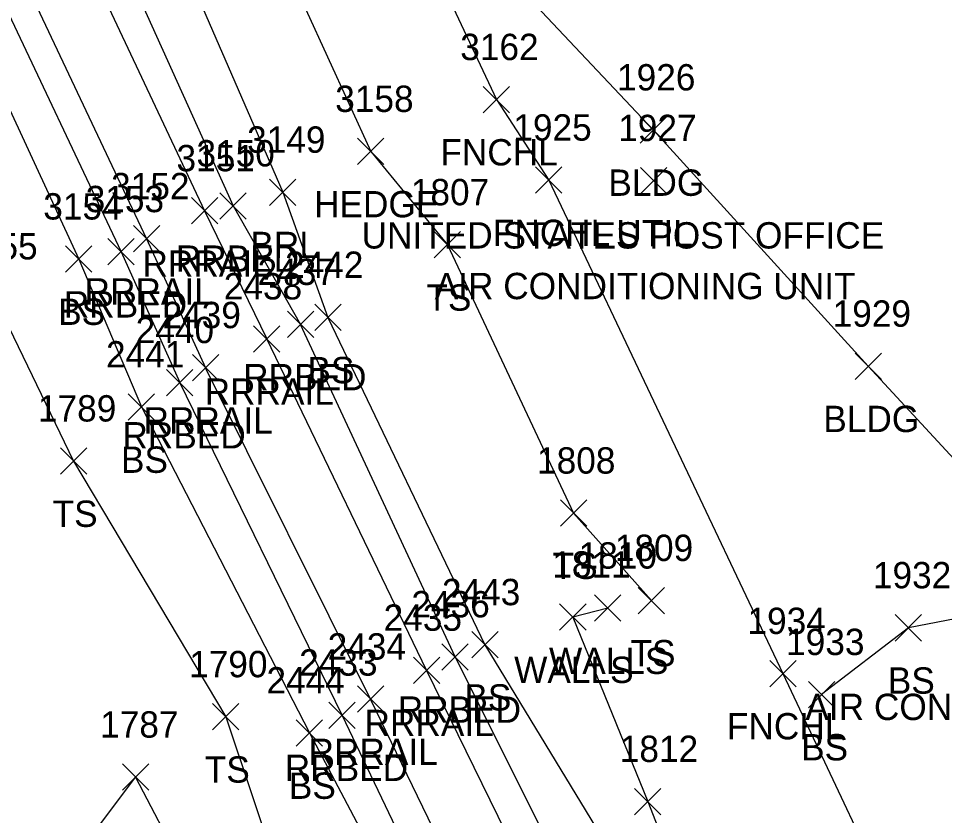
# Model space of a CAD drawing. Extents: x 1462668 to 1465147, y 550359 to 557351.
# Drawn here: x 1464582.5 to 1464652.8, y 552792.1 to 552852.6 of the extents above; entities that cross this region are included whole.
import ezdxf

# ---------------------------------------------------------------- set-up
doc = ezdxf.new("R2010")
doc.units = 0
for name, color, linetype in [('L_A', 7, 'Continuous'), ('L_C', 7, 'Continuous'), ('L_I', 7, 'Continuous'), ('L_TIC', 7, 'Continuous'), ('LABL', 7, 'Continuous'), ('LAHR', 7, 'Continuous'), ('LAPB', 7, 'Continuous'), ('LBC', 7, 'Continuous'), ('LELB', 7, 'Continuous'), ('Level 6', 7, 'Continuous'), ('LFNC', 7, 'Continuous'), ('LWS', 7, 'Continuous'), ('R_A', 7, 'Continuous'), ('R_I', 7, 'Continuous'), ('R_TIC', 7, 'Continuous'), ('RR', 7, 'Continuous'), ('RRB', 7, 'Continuous'), ('U_A', 7, 'Continuous'), ('U_C', 7, 'Continuous'), ('U_I', 7, 'Continuous'), ('UDEFAULT', 7, 'Continuous')]:
    doc.layers.add(name, color=color, linetype=linetype)

msp = doc.modelspace()

# ---------------------------------------------------------------- linework, layer by layer
at = {"layer": 'L_TIC'}
for points in [[(1464617.773, 552845.489), (1464619.773, 552847.489)], [(1464619.773, 552845.489), (1464617.773, 552847.489)], [(1464629.683, 552843.183), (1464631.683, 552845.183)], [(1464631.683, 552843.183), (1464629.683, 552845.183)], [(1464608.234, 552841.55), (1464610.234, 552843.55)], [(1464610.234, 552841.55), (1464608.234, 552843.55)], [(1464621.755, 552839.374), (1464623.755, 552841.374)], [(1464623.755, 552839.374), (1464621.755, 552841.374)], [(1464601.556, 552838.454), (1464603.556, 552840.454)], [(1464603.556, 552838.454), (1464601.556, 552840.454)], [(1464614.054, 552834.465), (1464616.054, 552836.465)], [(1464616.054, 552834.465), (1464614.054, 552836.465)], [(1464586.074, 552833.384), (1464588.074, 552835.384)], [(1464588.074, 552833.384), (1464586.074, 552835.384)], [(1464604.992, 552828.954), (1464606.992, 552830.954)], [(1464606.992, 552828.954), (1464604.992, 552830.954)], [(1464646, 552825.245), (1464648, 552827.245)], [(1464648, 552825.245), (1464646, 552827.245)], [(1464590.837, 552822.151), (1464592.837, 552824.151)], [(1464592.837, 552822.151), (1464590.837, 552824.151)], [(1464585.679, 552818.048), (1464587.679, 552820.048)], [(1464587.679, 552818.048), (1464585.679, 552820.048)], [(1464623.634, 552814.092), (1464625.634, 552816.092)], [(1464625.634, 552814.092), (1464623.634, 552816.092)], [(1464629.546, 552807.458), (1464631.546, 552809.458)], [(1464631.546, 552807.458), (1464629.546, 552809.458)], [(1464626.227, 552806.88), (1464628.227, 552808.88)], [(1464628.227, 552806.88), (1464626.227, 552808.88)], [(1464623.579, 552806.197), (1464625.579, 552808.197)], [(1464625.579, 552806.197), (1464623.579, 552808.197)], [(1464649.048, 552805.384), (1464651.048, 552807.384)], [(1464651.048, 552805.384), (1464649.048, 552807.384)], [(1464616.903, 552804.102), (1464618.903, 552806.102)], [(1464618.903, 552804.102), (1464616.903, 552806.102)], [(1464639.528, 552801.915), (1464641.528, 552803.915)], [(1464641.528, 552801.915), (1464639.528, 552803.915)], [(1464642.461, 552800.318), (1464644.461, 552802.318)], [(1464644.461, 552800.318), (1464642.461, 552802.318)], [(1464597.233, 552798.631), (1464599.233, 552800.631)], [(1464599.233, 552798.631), (1464597.233, 552800.631)], [(1464603.584, 552797.4), (1464605.584, 552799.4)], [(1464605.584, 552797.4), (1464603.584, 552799.4)], [(1464590.39, 552794.047), (1464592.39, 552796.047)], [(1464592.39, 552794.047), (1464590.39, 552796.047)], [(1464629.268, 552792.197), (1464631.268, 552794.197)], [(1464631.268, 552792.197), (1464629.268, 552794.197)]]:
    msp.add_lwpolyline(points, dxfattribs=at)
at = {"layer": 'LABL'}
for points in [[(1464521.817, 553014.257), (1464534.421, 552986.479), (1464548.756, 552956.476), (1464566.046, 552923.715), (1464584.095, 552881.95), (1464602.556, 552839.454)], [(1464602.556, 552839.454), (1464605.992, 552829.954)]]:
    msp.add_lwpolyline(points, dxfattribs=at)
at = {"layer": 'LAHR'}
for points in [[(1464554.676, 552968.433), (1464574.685, 552927.615), (1464586.069, 552906.261), (1464589.517, 552885.704), (1464609.234, 552842.55)], [(1464609.234, 552842.55), (1464615.054, 552835.465)]]:
    msp.add_lwpolyline(points, dxfattribs=at)
at = {"layer": 'LAPB'}
msp.add_lwpolyline([(1464577.377, 552765.621), (1464580.729, 552777.148), (1464584.496, 552785.852), (1464591.39, 552795.047), (1464598.324, 552781.79)], dxfattribs=at)
at = {"layer": 'LBC'}
msp.add_lwpolyline([(1464630.683, 552844.183), (1464647, 552826.245), (1464662.824, 552809.12), (1464674.135, 552796.541), (1464676.046, 552794.385), (1464676.323, 552794.22), (1464680.599, 552789.69), (1464684.238, 552785.637), (1464687.25, 552782.346), (1464688.423, 552780.98), (1464688.685, 552780.857), (1464693.228, 552781.087), (1464696.717, 552777.657), (1464709.319, 552789.166), (1464719.872, 552798.972), (1464732.78, 552810.229), (1464729.33, 552814.126), (1464731.934, 552816.516), (1464730.162, 552818.565), (1464729.963, 552818.738), (1464700.001, 552851.131)], dxfattribs=at)
at = {"layer": 'LELB'}
for points in [[(1464320.567, 553552.858), (1464335.76, 553496.578), (1464351.011, 553439.579), (1464352.003, 553433.56), (1464356.912, 553435.892), (1464366.085, 553404.903), (1464375.786, 553365.63), (1464378.907, 553354.302), (1464392.497, 553314.304), (1464410.738, 553264.077), (1464424.646, 553220.178), (1464446.714, 553164.768), (1464462.562, 553121.255), (1464478.696, 553079.343), (1464487.037, 553051.034), (1464509.441, 553004.952), (1464519.166, 552979.765), (1464533.373, 552948.388), (1464548.853, 552915.726), (1464568.294, 552875.055), (1464587.074, 552834.384)], [(1464615.054, 552835.465), (1464624.634, 552815.092), (1464630.546, 552808.458)], [(1464587.074, 552834.384), (1464591.837, 552823.151)], [(1464580.696, 552831.355), (1464586.679, 552819.048)], [(1464605.992, 552829.954), (1464617.903, 552805.102), (1464635.924, 552775.462), (1464644.18, 552750.936), (1464670.761, 552698.112)], [(1464591.837, 552823.151), (1464604.584, 552798.4), (1464620.531, 552768.212), (1464633.366, 552738.896), (1464646.04, 552708.211), (1464657.171, 552677.902), (1464659.575, 552669.465), (1464660.96, 552669.665)], [(1464586.679, 552819.048), (1464598.233, 552799.631), (1464602.504, 552786.853), (1464616.573, 552757.355), (1464624.782, 552742.85), (1464627.676, 552737.431)], [(1464662.378, 552808.761), (1464650.048, 552806.384), (1464643.461, 552801.318)]]:
    msp.add_lwpolyline(points, dxfattribs=at)
at = {"layer": 'Level 6'}
msp.add_lwpolyline([(1464732.78, 552810.229), (1464719.872, 552798.972), (1464709.319, 552789.166), (1464696.717, 552777.657), (1464693.228, 552781.087), (1464688.685, 552780.857), (1464688.423, 552780.98), (1464687.25, 552782.346), (1464684.238, 552785.637), (1464680.599, 552789.69), (1464676.323, 552794.22), (1464674.135, 552796.541), (1464662.824, 552809.12), (1464647, 552826.245), (1464630.683, 552844.183), (1464609.102, 552867.098), (1464596.699, 552882.351), (1464588.04, 552907.529), (1464577.161, 552929.547), (1464572.243, 552959.724), (1464572.671, 552990.205)], dxfattribs=at)
at = {"layer": 'LFNC'}
for points in [[(1464532.76, 553019.043), (1464546.496, 552992.349), (1464558.706, 552966.787), (1464577.161, 552929.547), (1464588.04, 552907.529), (1464596.699, 552882.351), (1464602.125, 552866.643), (1464609.102, 552867.098), (1464618.773, 552846.489)], [(1464618.773, 552846.489), (1464622.755, 552840.374)], [(1464622.755, 552840.374), (1464640.528, 552802.915), (1464653.99, 552774.381), (1464678.707, 552725.755), (1464681.909, 552714.313)]]:
    msp.add_lwpolyline(points, dxfattribs=at)
at = {"layer": 'LWS'}
msp.add_lwpolyline([(1464627.227, 552807.88), (1464624.579, 552807.197), (1464630.268, 552793.197), (1464640.043, 552768.12), (1464646.829, 552754.919), (1464648.101, 552754.433), (1464659.033, 552736.713), (1464665.52, 552721.715), (1464672.421, 552707.566), (1464674.293, 552701.543), (1464673.431, 552699.034)], dxfattribs=at)
at = {"layer": 'R_TIC'}
for points in [[(1464597.79, 552837.414), (1464599.79, 552839.414)], [(1464599.79, 552837.414), (1464597.79, 552839.414)], [(1464595.621, 552837.046), (1464597.621, 552839.046)], [(1464597.621, 552837.046), (1464595.621, 552839.046)], [(1464591.225, 552834.923), (1464593.225, 552836.923)], [(1464593.225, 552834.923), (1464591.225, 552836.923)], [(1464589.293, 552833.942), (1464591.293, 552835.942)], [(1464591.293, 552833.942), (1464589.293, 552835.942)], [(1464602.908, 552828.416), (1464604.908, 552830.416)], [(1464604.908, 552828.416), (1464602.908, 552830.416)], [(1464600.343, 552827.316), (1464602.343, 552829.316)], [(1464602.343, 552827.316), (1464600.343, 552829.316)], [(1464595.703, 552825.136), (1464597.703, 552827.136)], [(1464597.703, 552825.136), (1464595.703, 552827.136)], [(1464593.744, 552824), (1464595.744, 552826)], [(1464595.744, 552824), (1464593.744, 552826)], [(1464614.641, 552803.178), (1464616.641, 552805.178)], [(1464616.641, 552803.178), (1464614.641, 552805.178)], [(1464612.477, 552802.16), (1464614.477, 552804.16)], [(1464614.477, 552802.16), (1464612.477, 552804.16)], [(1464608.228, 552799.971), (1464610.228, 552801.971)], [(1464610.228, 552799.971), (1464608.228, 552801.971)], [(1464606.066, 552798.752), (1464608.066, 552800.752)], [(1464608.066, 552798.752), (1464606.066, 552800.752)]]:
    msp.add_lwpolyline(points, dxfattribs=at)
at = {"layer": 'RR'}
for points in [[(1464329.227, 553555.383), (1464346.959, 553499.526), (1464365.931, 553439.424), (1464375.443, 553408.882), (1464392.353, 553356.138), (1464404.616, 553317.704), (1464421.027, 553267.802), (1464435.667, 553224.383), (1464455.628, 553167.93), (1464471.443, 553125.328), (1464488.07, 553083.008), (1464498.631, 553056.822), (1464517.453, 553011.952), (1464529.395, 552984.226), (1464543.059, 552953.498), (1464558.282, 552920.118), (1464577.458, 552878.669), (1464596.621, 552838.046)], [(1464324.555, 553553.944), (1464342.167, 553498.072), (1464361.292, 553437.522), (1464370.776, 553407.016), (1464387.3, 553355.343), (1464399.888, 553316.176), (1464416.453, 553266.264), (1464431.113, 553222.566), (1464450.962, 553166.17), (1464466.848, 553123.461), (1464483.538, 553081.048), (1464493.972, 553055.168), (1464513.542, 553008.432), (1464524.983, 552981.815), (1464538.762, 552951.059), (1464553.982, 552917.82), (1464573.128, 552876.248), (1464592.225, 552835.923)], [(1464596.621, 552838.046), (1464601.343, 552828.316)], [(1464592.225, 552835.923), (1464596.703, 552826.136)], [(1464849.389, 552249.534), (1464842.819, 552270.793), (1464835.11, 552294.838), (1464826.262, 552322.52), (1464813.909, 552358.251), (1464808.668, 552373.872), (1464804.992, 552384.746), (1464790.19, 552425.007), (1464777.181, 552458.665), (1464762.364, 552494.605), (1464744.909, 552535.145), (1464735.628, 552555.847), (1464721.293, 552586.6), (1464702.021, 552626.346), (1464686.842, 552656.687), (1464671.35, 552687.141), (1464662.335, 552704.74), (1464642.534, 552744.081), (1464629.159, 552771.135), (1464613.477, 552803.16), (1464601.343, 552828.316)], [(1464844.813, 552247.755), (1464838.177, 552269.149), (1464830.386, 552293.617), (1464821.392, 552321.548), (1464809.517, 552356.645), (1464804.149, 552372.473), (1464800.295, 552383.078), (1464785.596, 552423.206), (1464772.719, 552456.472), (1464757.811, 552492.705), (1464740.233, 552533.386), (1464731.218, 552553.662), (1464716.736, 552584.611), (1464697.665, 552624.112), (1464682.453, 552654.497), (1464666.878, 552684.945), (1464657.727, 552702.874), (1464638.134, 552741.98), (1464624.708, 552768.998), (1464609.228, 552800.971), (1464596.703, 552826.136)]]:
    msp.add_lwpolyline(points, dxfattribs=at)
at = {"layer": 'RRB'}
for points in [[(1464320.567, 553552.858), (1464339.05, 553497.299), (1464359.102, 553436.849), (1464368.452, 553406.111), (1464384.327, 553354.986), (1464397.563, 553315.408), (1464413.048, 553265.366), (1464427.983, 553221.445), (1464449.131, 553165.586), (1464464.664, 553122.352), (1464481.224, 553080.022), (1464490.894, 553052.761), (1464510.863, 553007.552), (1464522.316, 552980.594), (1464536.188, 552949.724), (1464551.426, 552916.631), (1464570.989, 552875.749), (1464590.293, 552834.942)], [(1464345.31, 553519.908), (1464352.279, 553501.122), (1464369.887, 553440.754), (1464378.638, 553409.812), (1464396.8, 553355.407), (1464407.98, 553318.651), (1464422.767, 553268.535), (1464437.567, 553224.949), (1464457.686, 553168.589), (1464473.625, 553125.967), (1464490.255, 553084.118), (1464501.176, 553057.708), (1464519.383, 553013.043), (1464531.698, 552984.969), (1464545.352, 552954.916), (1464560.689, 552920.935), (1464579.899, 552880.239), (1464598.79, 552838.414)], [(1464598.79, 552838.414), (1464603.908, 552829.416)], [(1464590.293, 552834.942), (1464594.744, 552825)], [(1464851.042, 552250.445), (1464845.147, 552271.635), (1464837.544, 552295.462), (1464828.768, 552323.575), (1464816.78, 552359.11), (1464810.928, 552374.769), (1464807.843, 552386.028), (1464792.774, 552426.038), (1464778.944, 552461.754), (1464771.168, 552477.614), (1464764.619, 552495.611), (1464747.04, 552536.302), (1464737.618, 552557.165), (1464723.44, 552587.94), (1464704.535, 552627.922), (1464689.191, 552657.618), (1464673.574, 552688.335), (1464664.014, 552705.151), (1464644.495, 552745.11), (1464631.556, 552772.375), (1464615.641, 552804.178), (1464603.908, 552829.416)], [(1464842.442, 552246.931), (1464836.486, 552268.553), (1464828.066, 552292.901), (1464819.091, 552320.895), (1464807.286, 552355.87), (1464801.457, 552371.532), (1464797.599, 552381.724), (1464783.012, 552422.471), (1464769.406, 552454.584), (1464755.315, 552491.81), (1464738.611, 552532.376), (1464729.391, 552552.755), (1464715, 552583.837), (1464695.071, 552622.976), (1464679.554, 552652.995), (1464663.948, 552683.282), (1464654.855, 552701.899), (1464635.344, 552740.456), (1464622.383, 552767.72), (1464607.066, 552799.752), (1464594.744, 552825)]]:
    msp.add_lwpolyline(points, dxfattribs=at)
at = {"layer": 'UDEFAULT'}
for points in [[(1464629.718, 552839.337), (1464631.718, 552841.337)], [(1464631.718, 552839.337), (1464629.718, 552841.337)]]:
    msp.add_lwpolyline(points, dxfattribs=at)

# ---------------------------------------------------------------- texts
at = {"layer": 'L_A'}
for s, p in [('FNCHL', (1464614.522, 552841.489)), ('BLDG', (1464627.273, 552839.183)), ('HEDGE', (1464604.934, 552837.55)), ('FNCHL', (1464618.504, 552835.374)), ('BRL', (1464600.1, 552834.454)), ('TS', (1464613.463, 552830.465)), ('BS', (1464585.515, 552829.384)), ('BS', (1464604.433, 552824.954)), ('BLDG', (1464643.59, 552821.245)), ('BS', (1464590.278, 552818.151)), ('TS', (1464585.089, 552814.048)), ('TS', (1464623.043, 552810.092)), ('WALLS', (1464622.77, 552802.88)), ('TS', (1464628.955, 552803.458)), ('WALLS', (1464620.123, 552802.197)), ('BS', (1464648.488, 552801.384)), ('BS', (1464616.344, 552800.102)), ('FNCHL', (1464636.276, 552797.915)), ('BS', (1464641.902, 552796.318)), ('TS', (1464596.642, 552794.631)), ('BS', (1464603.025, 552793.4))]:
    msp.add_text(s, height=2, dxfattribs=at).set_placement(p)
at = {"layer": 'L_C'}
msp.add_text('UNITED STATES POST OFFICE', height=2, dxfattribs=at).set_placement((1464608.541, 552835.183))
at = {"layer": 'L_I'}
for s, p in [('3162', (1464616.033, 552849.489)), ('1926', (1464627.935, 552847.183)), ('3158', (1464606.541, 552845.55)), ('1925', (1464620.063, 552843.374)), ('3149', (1464599.855, 552842.454)), ('1807', (1464612.282, 552838.465)), ('3154', (1464584.381, 552837.384)), ('3155', (1464578.004, 552834.355)), ('2442', (1464602.732, 552832.954)), ('1929', (1464644.299, 552829.245)), ('2441', (1464589.144, 552826.151)), ('1789', (1464583.978, 552822.048)), ('1808', (1464621.862, 552818.092)), ('1809', (1464627.766, 552811.458)), ('1810', (1464625.014, 552810.88)), ('1811', (1464623.02, 552810.197)), ('1932', (1464647.355, 552809.384)), ('2443', (1464614.643, 552808.102)), ('1934', (1464637.835, 552805.915)), ('1933', (1464640.768, 552804.318)), ('1790', (1464595.453, 552802.631)), ('2444', (1464601.324, 552801.4)), ('1787', (1464588.697, 552798.047)), ('1812', (1464628.142, 552796.197))]:
    msp.add_text(s, height=2, dxfattribs=at).set_placement(p)
at = {"layer": 'R_A'}
for s, p in [('RRBED', (1464594.436, 552833.414)), ('RRRAIL', (1464591.913, 552833.046)), ('RRRAIL', (1464587.517, 552830.923)), ('RRBED', (1464585.939, 552829.942)), ('RRBED', (1464599.553, 552824.416)), ('RRRAIL', (1464596.634, 552823.316)), ('RRRAIL', (1464591.994, 552821.136)), ('RRBED', (1464590.39, 552820)), ('RRBED', (1464611.286, 552799.178)), ('RRRAIL', (1464608.768, 552798.16)), ('RRRAIL', (1464604.519, 552795.971)), ('RRBED', (1464602.712, 552794.752))]:
    msp.add_text(s, height=2, dxfattribs=at).set_placement(p)
at = {"layer": 'R_I'}
for s, p in [('3151', (1464594.495, 552841.046)), ('3150', (1464596.011, 552841.414)), ('3152', (1464589.533, 552838.923)), ('3153', (1464587.6, 552837.942)), ('2437', (1464600.648, 552832.416)), ('2438', (1464598.083, 552831.316)), ('2439', (1464593.435, 552829.136)), ('2440', (1464591.398, 552828)), ('2436', (1464612.326, 552807.178)), ('2435', (1464610.217, 552806.16)), ('2434', (1464605.968, 552803.971)), ('2433', (1464603.806, 552802.752))]:
    msp.add_text(s, height=2, dxfattribs=at).set_placement(p)
at = {"layer": 'U_A'}
msp.add_text('UTIL', height=2, dxfattribs=at).set_placement((1464627.883, 552835.337))
at = {"layer": 'U_C'}
for p in [(1464614.096, 552831.337), (1464642.231, 552799.383)]:
    msp.add_text('AIR CONDITIONING UNIT', height=2, dxfattribs=at).set_placement(p)
at = {"layer": 'U_I'}
msp.add_text('1927', height=2, dxfattribs=at).set_placement((1464628.025, 552843.337))

doc.saveas('drawing.dxf')
